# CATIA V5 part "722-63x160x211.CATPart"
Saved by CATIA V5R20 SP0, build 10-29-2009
Part number: 722-63x160x211
Definition: NONE
Nomenclature: 722-63x160x211
Source: Unknown
Description: 722-63x160x211
Bounding box of the stored display mesh (mm): x -31.5 to 31.5, y -31.5 to 31.5, z -142 to 69
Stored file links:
  C:\Users\Utente\Desktop\IO LAVORO\3D X SITO CF\X SITO\722\722-63x160x211.CATPart
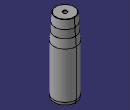
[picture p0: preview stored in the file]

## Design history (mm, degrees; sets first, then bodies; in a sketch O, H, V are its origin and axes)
Body1 "722-63x160x211" (main body)
  Solid1: solid without history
